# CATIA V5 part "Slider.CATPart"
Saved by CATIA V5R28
Part number: Slider
Bounding box of the stored display mesh (mm): x -50 to 50, y -20 to 20, z -27.5 to 27.5
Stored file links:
  C:\Users\Parisa\Desktop\tarah sanat\CAR JACK\Slider.CATPart
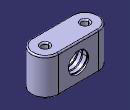
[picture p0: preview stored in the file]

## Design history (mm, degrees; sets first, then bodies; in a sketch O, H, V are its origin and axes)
Body1 (main body)
  Sketch1 on xy-plane, origin (0, 0, 0), H (1, 0, 0), V (0, 1, 0)
    construction line L1 (-30, 0) -> (30, 0)
    point P1 (-30, 0)
    point P2 (30, 0)
    line L2 (-30, 20) -> (30, 20)
    line L3 (30, -20) -> (-30, -20)
    arc A1 centre (30, 0) radius 20 from (30, 20) to (30, -20) cw
    arc A2 centre (-30, 0) radius 20 from (-30, -20) to (-30, 20) cw
    circle A3 centre (30, 0) radius 5
    circle A4 centre (-30, 0) radius 5
    distance L1 L2 = 20
    length L2 = 60
    radius A4 = 5
    radius A3 = 5
    coincidence: P1 H
    horizontal: L1 H
    tangency: A1 L2, A2 L2, A1 L3, A2 L3
    symmetry: P1 P2 V
  Pad1: profile Sketch1, direction (0, 0, 1), length 27.5, mirrored extent
  Sketch2 on face of Pad1 from Sketch1.L2, origin (0, 20, 0), H (-1, 0, 0), V (0, 0, 1)
    circle A1 centre (0, 0) radius 15
    radius A1 = 15
  Pocket1: profile Sketch2, direction (0, -1, 0), through (limit type 6)
  Helix1: Direction Y axis, RefPoint {point type OnCurve, Support edge [face of Pad1 from Sketch1.L2 | face of Pocket1 from Sketch2.A1], RefPoint {extremum Reference edge [face of Pad1 from Sketch1.L2 | face of Pocket1 from Sketch2.A1], Direction (1, 2, 3)}, Length 0}, Pitch 7, Height 40, TaperAngle 0, Revolutions 1
  Plane1: type 1Line1Pt, RefPoint vertex of Helix1, Line Y axis
  Sketch3 on Plane1, origin (0, 0, 0), H (0, 1, 0), V (0.3162, 0, 0.9487)
    point P1 (20, 15)
    line L1 (20.75, 15.75) -> (20.75, 14.25)
    line L2 (20.75, 14.25) -> (19.25, 14.25)
    line L3 (19.25, 14.25) -> (19.25, 15.75)
    line L4 (19.25, 15.75) -> (20.75, 15.75)
    reference projected point E1 (20, 15) from vertex of Helix1
    length L1 = 1.5
    length L4 = 1.5
    vertical: L1 V, L3 V
    horizontal: L2 H, L4 H
    equidistance: L1 L3 P1, L2 L4 P1
    coincidence: E1 P1
  Slot1: profile Sketch3, centre curve Helix1
  AutoFillet1: AutoFilletRadius 2, CurvatureRadius 1, RoundRadius 2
